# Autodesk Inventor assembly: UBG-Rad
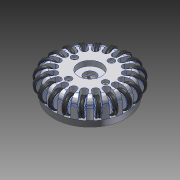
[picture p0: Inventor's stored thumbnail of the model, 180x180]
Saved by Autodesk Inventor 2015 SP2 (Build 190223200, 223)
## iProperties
Created: 2012-07
Part Number: UBG-Rad
Document SubType Name: Assembly
Designer: rYan
Mass: 99.5163 g
Surface Area: 288.799 cm^2
Volume: 21.9681 cm^3
Density: 4.53002 g/cm^3
Author: rYan
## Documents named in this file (9)
- D:\TIGERs GIT\Hardware\mechanik\2016\Inventor\Antrieb\UBG-Rad.iam
- D:\TIGERs GIT\Hardware\mechanik\2016\Inventor\Antrieb\Radkasten.ipt
- D:\TIGERs GIT\Hardware\mechanik\2016\Inventor\Antrieb\MG-Rolle mit Achse.iam
- D:\TIGERs GIT\Hardware\mechanik\2016\Inventor\Inhaltscenter\de-DE\DIN BEARING(1)\DIN 625 SKF - SKF 627.ipt
- D:\TIGERs GIT\Hardware\mechanik\2016\Inventor\Antrieb\Raddeckel.ipt
- D:\TIGERs GIT\Hardware\mechanik\2016\Inventor\Antrieb\Radwelle.ipt
- D:\TIGERs GIT\Hardware\mechanik\2016\Inventor\Kaufteile\Innenzahnrad z60.ipt
- D:\TIGERs GIT\Hardware\mechanik\2016\Inventor\Inhaltscenter\de-DE\ISO 4762(1)\ISO 4762 - M2 x 5DIN EN ISO.ipt
- D:\TIGERs GIT\Hardware\mechanik\2016\Inventor\Inhaltscenter\de-DE\ISO 2338(1)\ISO 2338 - 2 m6 x 6DIN EN.ipt
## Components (33 placed, 8 different names)
1. Radkasten:1 — Passend:1, Passend:2, Passend:3, Passend:5, Einfügen:1, Einfügen:2, Einfügen:3, Einfügen:4
2. DIN 625 SKF 627:1 — Passend:5, Passend:10, Passend:20
3. Raddeckel:1 — Einfügen:3, Einfügen:4
4. Radwelle:1 — Passend:10, Passend:20
5. Innenzahnrad z=60:1 — Einfügen:1, Einfügen:2
6. MG-Rolle mit Achse:1 [sub-assembly] — Passend:1, Passend:2, Passend:3
7. MG-Rolle mit Achse:2 [sub-assembly]
8. MG-Rolle mit Achse:3 [sub-assembly]
9. MG-Rolle mit Achse:4 [sub-assembly]
10. MG-Rolle mit Achse:5 [sub-assembly]
11. MG-Rolle mit Achse:6 [sub-assembly]
12. MG-Rolle mit Achse:7 [sub-assembly]
13. MG-Rolle mit Achse:8 [sub-assembly]
14. MG-Rolle mit Achse:9 [sub-assembly]
15. MG-Rolle mit Achse:10 [sub-assembly]
16. MG-Rolle mit Achse:11 [sub-assembly]
17. MG-Rolle mit Achse:12 [sub-assembly]
18. MG-Rolle mit Achse:13 [sub-assembly]
19. MG-Rolle mit Achse:14 [sub-assembly]
20. MG-Rolle mit Achse:15 [sub-assembly]
21. MG-Rolle mit Achse:16 [sub-assembly]
22. MG-Rolle mit Achse:17 [sub-assembly]
23. MG-Rolle mit Achse:18 [sub-assembly]
24. MG-Rolle mit Achse:19 [sub-assembly]
25. MG-Rolle mit Achse:20 [sub-assembly]
26. DIN EN ISO 2338 2 m6 x 6:1
27. DIN EN ISO 2338 2 m6 x 6:2
28. DIN EN ISO 2338 2 m6 x 6:3
29. DIN EN ISO 2338 2 m6 x 6:4
30. DIN EN ISO 4762 M2 x 5:1
31. DIN EN ISO 4762 M2 x 5:2
32. DIN EN ISO 4762 M2 x 5:3
33. DIN EN ISO 4762 M2 x 5:4
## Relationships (10: Mate 6, Insert 4)
- Passend:1 [Mate]: Radkasten:1 ↔ MG-Rolle mit Achse:1
- Passend:2 [Mate]: Radkasten:1 ↔ MG-Rolle mit Achse:1
- Passend:3 [Mate]: Radkasten:1 ↔ MG-Rolle mit Achse:1
- Passend:5 [Mate]: Radkasten:1 ↔ DIN 625 SKF 627:1
- Passend:10 [Mate]: DIN 625 SKF 627:1 ↔ Radwelle:1
- Einfügen:1 [Insert]: Radkasten:1 ↔ Innenzahnrad z=60:1
- Einfügen:2 [Insert]: Radkasten:1 ↔ Innenzahnrad z=60:1
- Einfügen:3 [Insert]: Radkasten:1 ↔ Raddeckel:1
- Einfügen:4 [Insert]: Radkasten:1 ↔ Raddeckel:1
- Passend:20 [Mate]: DIN 625 SKF 627:1 ↔ Radwelle:1
